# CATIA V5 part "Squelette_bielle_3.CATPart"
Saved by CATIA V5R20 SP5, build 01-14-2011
Part number: Squelette_bielle_3
Publications: "Longueur_bielle_3"
Bounding box of the stored display mesh (mm): x 0 to 22, y 0 to 20, z 0 to 0
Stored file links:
  C:\Users\MARLENE\Documents\IFMA\S3\IAO\Copie de CAO\Squelette_bielle_3.CATPart
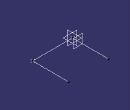
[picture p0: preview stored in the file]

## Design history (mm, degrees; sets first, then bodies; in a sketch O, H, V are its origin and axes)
Parameters
  Longueur_bielle_3 = 22 mm
Set1
  Point1: (0, 0, 0)
  Point2: (22 {= Longueur_bielle_3}, 0, 0)
  Line1: type PtPt, FirstPoint Point1, SecondPoint Point2
  Line2: type PtDir, RefPoint Point1, Direction zx-plane, Start 0, End 20
  Line3: type PtDir, RefPoint Point2, Direction zx-plane, Start 0, End 20
  Plane1: type Offset, RefPlane zx-plane, Offset 3
Body1 (main body)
